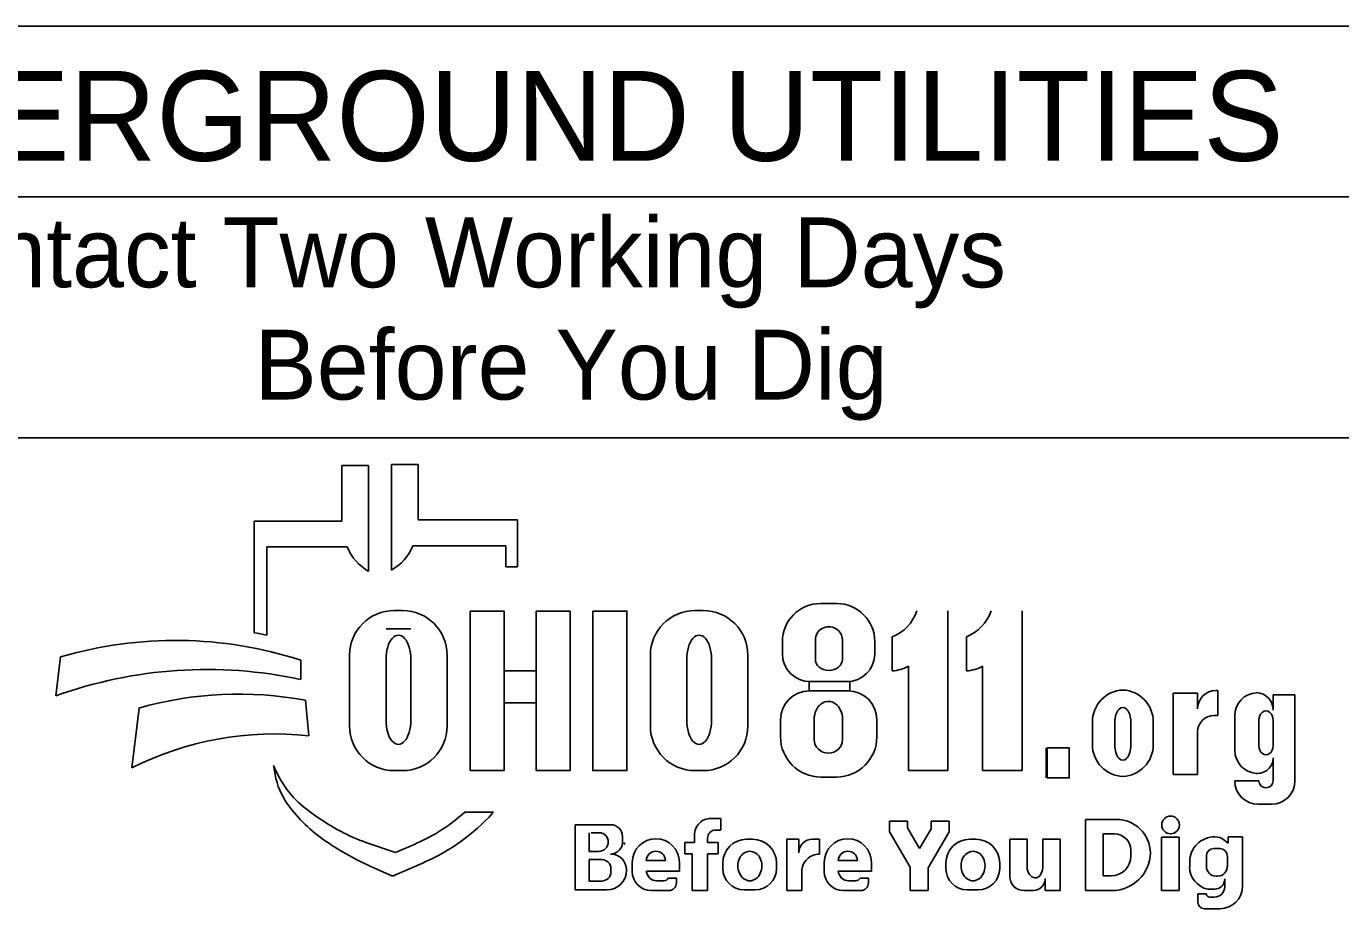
# Model space of a CAD drawing. Extents: x -1.2 to 34, y -8.5 to 22.
# Drawn here: x 15.565 to 18.2, y 1.501 to 3.27 of the extents above; entities that cross this region are included whole.
import ezdxf

# ---------------------------------------------------------------- set-up
doc = ezdxf.new("R2010")
doc.units = 0
doc.layers.add('SH_Data', color=7, linetype='Continuous')
doc.layers.add('SH_Text', color=7, linetype='Continuous')

msp = doc.modelspace()

# ---------------------------------------------------------------- linework, layer by layer
at = {"layer": 'SH_Data'}
for p, q in [((19.0916, 3.2703), (14.8416, 3.2703)), ((14.8416, 2.9287), (19.0916, 2.9287)), ((14.8416, 2.4453), (19.0916, 2.4453))]:
    msp.add_line(p, q, dxfattribs=at)
at = {"layer": 'SH_Text'}
for p, q in [((16.1976, 2.2783), (16.1976, 2.3897)), ((16.1976, 2.3897), (16.2513, 2.3897)), ((16.2513, 2.3897), (16.2513, 2.1777)), ((16.2969, 2.18), (16.2969, 2.3921)), ((16.2969, 2.3921), (16.3506, 2.3921)), ((16.3506, 2.3921), (16.3506, 2.2806)), ((16.0217, 2.0544), (16.0217, 2.2783)), ((16.0217, 2.2783), (16.1976, 2.2783)), ((16.3506, 2.2806), (16.5498, 2.2806)), ((16.5498, 2.2806), (16.5498, 2.1868)), ((16.0469, 2.2268), (16.0469, 2.05)), ((16.208, 2.2268), (16.0469, 2.2268)), ((16.5265, 2.2291), (16.3402, 2.2291)), ((16.5265, 2.1868), (16.5265, 2.2291)), ((16.5498, 2.1868), (16.5265, 2.1868)), ((17.1572, 2.1131), (17.1899, 2.1131)), ((16.3026, 2.0991), (16.3192, 2.0991)), ((16.9057, 2.0991), (16.9222, 2.0991)), ((17.4127, 2.0986), (17.4127, 1.7787)), ((17.5616, 2.0986), (17.5616, 1.7787)), ((16.3359, 2.0621), (16.2861, 2.0621)), ((17.0809, 2.0125), (17.0809, 2.0368)), ((17.147, 2.0011), (17.147, 2.0404)), ((17.2012, 2.0404), (17.2012, 2.0011)), ((17.2662, 2.0368), (17.2662, 2.0125)), ((17.3011, 1.9779), (17.3011, 2.0461)), ((17.45, 1.9779), (17.45, 2.0461)), ((15.6243, 1.9281), (15.6337, 2.0062)), ((16.2132, 1.8676), (16.2132, 2.0096)), ((16.4086, 2.0096), (16.4086, 1.8676)), ((16.8162, 1.8676), (16.8162, 2.0096)), ((17.0117, 2.0096), (17.0117, 1.8676)), ((16.115, 1.9997), (16.115, 1.9609)), ((16.2861, 1.879), (16.2861, 2.0013)), ((16.3359, 2.0013), (16.3359, 1.879)), ((16.8891, 1.879), (16.8891, 2.0013)), ((16.9389, 2.0013), (16.9389, 1.879)), ((17.3335, 1.7787), (17.3335, 1.9873)), ((17.4823, 1.7787), (17.4823, 1.9873)), ((17.2102, 1.9565), (17.1369, 1.9565)), ((17.1351, 1.9382), (17.2124, 1.9382)), ((17.9134, 1.9335), (17.8645, 1.9335)), ((17.8645, 1.9335), (17.8645, 1.7706)), ((17.9134, 1.902), (17.9134, 1.9335)), ((17.9541, 1.9387), (17.9501, 1.9387)), ((17.9541, 1.8888), (17.9541, 1.9387)), ((18.0649, 1.8994), (18.0649, 1.9304)), ((18.0649, 1.9304), (18.1085, 1.9304)), ((18.1085, 1.9304), (18.1085, 1.7575)), ((15.7761, 1.7835), (15.7908, 1.9037)), ((16.1249, 1.9191), (16.1312, 1.8481)), ((17.0772, 1.8462), (17.0772, 1.8803)), ((17.1447, 1.8403), (17.1447, 1.8812)), ((17.2015, 1.8812), (17.2015, 1.8403)), ((17.2703, 1.8803), (17.2703, 1.8462)), ((17.7025, 1.8304), (17.7025, 1.8758)), ((17.7476, 1.8296), (17.7476, 1.8758)), ((17.7797, 1.8758), (17.7797, 1.8296)), ((17.8247, 1.8758), (17.8247, 1.8304)), ((17.9464, 1.8888), (17.9541, 1.8888)), ((17.988, 1.8189), (17.988, 1.8885)), ((18.0364, 1.8282), (18.0364, 1.8793)), ((18.0649, 1.8793), (18.0649, 1.8282)), ((17.9134, 1.7706), (17.9134, 1.8558)), ((17.6096, 1.8237), (17.6096, 1.7636)), ((18.0649, 1.7575), (18.0649, 1.8039)), ((16.0638, 1.7706), (16.0608, 1.7886)), ((16.3192, 1.7781), (16.3026, 1.7781)), ((16.9222, 1.7781), (16.9057, 1.7781)), ((17.4127, 1.7787), (17.3335, 1.7787)), ((17.5616, 1.7787), (17.4823, 1.7787)), ((17.8645, 1.7706), (17.9134, 1.7706)), ((17.1893, 1.7653), (17.1581, 1.7653)), ((17.988, 1.7575), (18.0364, 1.7575)), ((16.4441, 1.6948), (16.5015, 1.6948)), ((18.0617, 1.7107), (18.0348, 1.7107)), ((16.6654, 1.539), (16.6654, 1.6697)), ((16.6654, 1.6697), (16.7366, 1.6697)), ((16.938, 1.6825), (16.9574, 1.6825)), ((16.9574, 1.6825), (16.9574, 1.6595)), ((17.296, 1.6769), (17.3318, 1.6769)), ((17.296, 1.6555), (17.296, 1.6769)), ((17.3318, 1.6769), (17.3318, 1.6633)), ((17.3318, 1.6633), (17.3559, 1.6219)), ((17.3559, 1.6219), (17.3791, 1.6618)), ((17.3791, 1.6618), (17.3791, 1.6769)), ((17.3791, 1.6769), (17.415, 1.6769)), ((17.415, 1.6769), (17.415, 1.6555)), ((17.6884, 1.6805), (17.7507, 1.6805)), ((17.6884, 1.5378), (17.6884, 1.6805)), ((16.2457, 1.6344), (16.3051, 1.6139)), ((16.6934, 1.6163), (16.6934, 1.6532)), ((16.7186, 1.6532), (16.6973, 1.6532)), ((16.7603, 1.646), (16.7603, 1.6381)), ((16.8854, 1.6112), (16.8854, 1.6341)), ((16.8854, 1.6341), (16.9047, 1.6341)), ((16.9047, 1.6341), (16.9047, 1.6446)), ((16.9308, 1.6426), (16.9308, 1.6341)), ((16.9308, 1.6341), (16.9524, 1.6341)), ((16.9574, 1.6591), (16.9473, 1.6591)), ((16.9524, 1.6341), (16.9524, 1.6112)), ((17.0092, 1.6407), (17.0213, 1.6407)), ((17.0895, 1.5378), (17.0895, 1.6405)), ((17.0895, 1.6405), (17.114, 1.6405)), ((17.114, 1.6405), (17.114, 1.6136)), ((17.1412, 1.6405), (17.1551, 1.6405)), ((17.1551, 1.6405), (17.1551, 1.6108)), ((17.3373, 1.5845), (17.296, 1.6555)), ((17.415, 1.6555), (17.3729, 1.5831)), ((17.4566, 1.6407), (17.4688, 1.6407)), ((17.5368, 1.6407), (17.5715, 1.6407)), ((17.5368, 1.5662), (17.5368, 1.6407)), ((17.5715, 1.6407), (17.5715, 1.5854)), ((17.6029, 1.5837), (17.6029, 1.6407)), ((17.6029, 1.6407), (17.6377, 1.6407)), ((17.6377, 1.6407), (17.6377, 1.5378)), ((17.7244, 1.5672), (17.7244, 1.6513)), ((17.7244, 1.6513), (17.7469, 1.6513)), ((17.8411, 1.6449), (17.8767, 1.6449)), ((17.8411, 1.5378), (17.8411, 1.6449)), ((17.8767, 1.6449), (17.8767, 1.5378)), ((17.9662, 1.6393), (17.9748, 1.6327)), ((17.9748, 1.6453), (18.0036, 1.6453)), ((17.9748, 1.6327), (17.9748, 1.6453)), ((17.9748, 1.6453), (18.0036, 1.6453)), ((18.0036, 1.6453), (18.0036, 1.5467)), ((16.3051, 1.6139), (16.3461, 1.6317)), ((16.7128, 1.6163), (16.6934, 1.6163)), ((16.9003, 1.6112), (16.8854, 1.6112)), ((16.9003, 1.5378), (16.9003, 1.6112)), ((16.9524, 1.6112), (16.9308, 1.6112)), ((16.9308, 1.6112), (16.9308, 1.5378)), ((17.7795, 1.6186), (17.7795, 1.6067)), ((17.9457, 1.6219), (17.9584, 1.6219)), ((16.2991, 1.5669), (16.2617, 1.5833)), ((16.3624, 1.5943), (16.2991, 1.5669)), ((16.6934, 1.5568), (16.6934, 1.5997)), ((16.6934, 1.5997), (16.7189, 1.5997)), ((16.737, 1.5816), (16.737, 1.5752)), ((16.78, 1.5758), (16.78, 1.5942)), ((16.8465, 1.5982), (16.808, 1.5982)), ((16.8745, 1.5942), (16.8745, 1.5765)), ((16.9614, 1.5821), (16.9614, 1.5929)), ((17.0691, 1.5929), (17.0691, 1.5821)), ((17.1649, 1.5758), (17.1649, 1.5942)), ((17.2315, 1.5982), (17.1929, 1.5982)), ((17.2594, 1.5942), (17.2594, 1.5765)), ((17.3373, 1.5378), (17.3373, 1.5845)), ((17.3729, 1.5831), (17.3729, 1.5378)), ((17.4088, 1.5821), (17.4088, 1.5929)), ((17.5166, 1.5929), (17.5166, 1.5821)), ((17.8976, 1.5853), (17.8976, 1.5954)), ((17.9311, 1.586), (17.9311, 1.6073)), ((17.9731, 1.6073), (17.9731, 1.586)), ((16.7187, 1.5568), (16.6934, 1.5568)), ((16.7684, 1.5787), (16.7684, 1.5783)), ((16.8745, 1.5765), (16.8081, 1.5765)), ((16.829, 1.5573), (16.8431, 1.5573)), ((16.8517, 1.5629), (16.8685, 1.5629)), ((16.8685, 1.5629), (16.8685, 1.553)), ((17.12, 1.5759), (17.12, 1.5378)), ((17.2594, 1.5765), (17.193, 1.5765)), ((17.2139, 1.5573), (17.228, 1.5573)), ((17.2366, 1.5629), (17.2535, 1.5629)), ((17.2535, 1.5629), (17.2535, 1.553)), ((17.608, 1.5378), (17.608, 1.5619)), ((17.74, 1.5672), (17.7244, 1.5672)), ((17.9537, 1.5667), (17.9504, 1.5667)), ((17.9679, 1.5457), (17.9679, 1.561)), ((16.7291, 1.539), (16.6654, 1.539)), ((16.8533, 1.5378), (16.8179, 1.5378)), ((16.9308, 1.5378), (16.9003, 1.5378)), ((17.0264, 1.5393), (17.0042, 1.5393)), ((17.12, 1.5378), (17.0895, 1.5378)), ((17.2382, 1.5378), (17.2028, 1.5378)), ((17.3729, 1.5378), (17.3373, 1.5378)), ((17.4738, 1.5393), (17.4516, 1.5393)), ((17.584, 1.5378), (17.5652, 1.5378)), ((17.6377, 1.5378), (17.608, 1.5378)), ((17.742, 1.5378), (17.6884, 1.5378)), ((17.8767, 1.5378), (17.8411, 1.5378)), ((17.9141, 1.5145), (17.9141, 1.5315)), ((17.9141, 1.5315), (17.9311, 1.5315)), ((17.9476, 1.5406), (17.9339, 1.5406)), ((17.9379, 1.5245), (17.9468, 1.5245)), ((17.9583, 1.5014), (17.9272, 1.5014))]:
    msp.add_line(p, q, dxfattribs=at)
for points in [[(16.4551, 2.098), (16.523, 2.098), (16.523, 1.7781), (16.4551, 1.7781)], [(16.5872, 2.098), (16.6552, 2.098), (16.6552, 1.7781), (16.5872, 1.7781)], [(16.7005, 2.098), (16.7693, 2.098), (16.7693, 1.7781), (16.7005, 1.7781)], [(16.523, 1.9781), (16.5872, 1.9781), (16.5872, 1.9141), (16.523, 1.9141)], [(17.1347, 1.9565), (17.2164, 1.9565), (17.2164, 1.938), (17.1347, 1.938)], [(17.6121, 1.8237), (17.6562, 1.8237), (17.6562, 1.7636), (17.6121, 1.7636)]]:
    msp.add_lwpolyline(points, close=True, dxfattribs=at)
msp.add_circle((17.8593, 1.6692), 0.0177, dxfattribs=at)
for centre, radius, start, end in [((16.2994, 2.2636), 0.0985, 201.9296, 240.7469), ((16.2488, 2.2659), 0.0985, 299.2531, 338.0704), ((17.1572, 2.0368), 0.0763, 90, 180), ((17.1899, 2.0368), 0.0763, 0, 90), ((16.3026, 2.0096), 0.0895, 90, 180), ((16.3192, 2.0096), 0.0895, 0, 90), ((16.9057, 2.0096), 0.0895, 90, 180), ((16.9222, 2.0096), 0.0895, 0, 90), ((17.2672, 2.1278), 0.0885, 292.5572, 340.7355), ((17.416, 2.1278), 0.0885, 292.5572, 340.7355), ((15.8638, 1.2201), 0.8191, 72.1402, 106.3144), ((15.8935, 1.2454), 0.8191, 79.2074, 81.0007), ((17.1369, 2.0125), 0.056, 180, 270), ((17.2102, 2.0125), 0.056, 270, 0), ((15.9268, 1.089), 0.8919, 77.8238, 109.8274), ((17.2932, 2.0661), 0.0885, 275.1733, 297.0931), ((17.442, 2.0661), 0.0885, 275.1733, 297.0931), ((15.9907, 1.1993), 0.7322, 79.44, 105.8467), ((17.1351, 1.8803), 0.0579, 90, 180), ((17.2124, 1.8803), 0.0579, 0, 90), ((17.7665, 1.8758), 0.064, 92.5886, 180), ((17.7607, 1.8758), 0.064, 0, 87.4114), ((17.9501, 1.902), 0.0367, 90, 180), ((18.0339, 1.8885), 0.0459, 92.6865, 180), ((18.0299, 1.8994), 0.0351, 0, 86.9262), ((17.9464, 1.8558), 0.033, 90, 180), ((16.0628, 1.2161), 0.6357, 83.8248, 116.8021), ((16.3026, 1.8676), 0.0895, 180, 270), ((16.3192, 1.8676), 0.0895, 270, 0), ((16.9057, 1.8676), 0.0895, 180, 270), ((16.9222, 1.8676), 0.0895, 270, 0), ((17.1581, 1.8462), 0.081, 180, 270), ((17.1893, 1.8462), 0.081, 270, 0), ((17.7665, 1.8304), 0.064, 180, 267.4114), ((17.7607, 1.8304), 0.064, 272.5886, 0), ((18.0343, 1.8189), 0.0463, 180, 265.7132), ((18.0337, 1.8039), 0.0313, 264.7825, 0), ((16.2482, 1.8607), 0.2008, 201.0457, 232.5314), ((16.2051, 1.7947), 0.1433, 189.6817, 216.0884), ((18.0348, 1.7575), 0.0468, 180, 270), ((18.0617, 1.7575), 0.0468, 270, 0), ((16.3388, 1.8922), 0.3088, 216.0884, 235.7167), ((16.4407, 2.1119), 0.5173, 232.5314, 241.794), ((16.2027, 1.9622), 0.3602, 293.4582, 312.0712), ((16.2027, 1.9622), 0.401, 293.4582, 317.8286), ((16.7366, 1.646), 0.0238, 0, 90), ((16.938, 1.649), 0.0335, 90, 187.5187), ((17.7507, 1.6123), 0.0682, 0.9944, 90), ((16.5053, 2.1364), 0.6044, 235.7167, 246.2325), ((16.3555, 1.9531), 0.3371, 241.794, 250.9821), ((16.7128, 1.635), 0.0187, 270, 2.0582), ((16.7146, 1.6363), 0.0169, 357.8325, 90), ((16.7362, 1.6353), 0.0243, 270, 6.6529), ((16.8272, 1.5942), 0.0473, 0, 180), ((16.9473, 1.6426), 0.0165, 90, 180), ((17.0092, 1.5929), 0.0478, 90, 180), ((17.0213, 1.5929), 0.0478, 0, 90), ((17.1409, 1.6136), 0.0269, 89.2449, 180), ((17.2121, 1.5942), 0.0473, 0, 180), ((17.4566, 1.5929), 0.0478, 90, 180), ((17.4688, 1.5929), 0.0478, 0, 90), ((17.7469, 1.6186), 0.0327, 0, 90), ((17.9475, 1.5954), 0.0499, 89.0934, 180), ((17.9489, 1.617), 0.0283, 52.1415, 91.2046), ((16.7363, 1.5789), 0.0321, 4.0748, 90), ((16.7468, 1.6338), 0.0175, 347.4023, 0), ((16.8273, 1.5972), 0.0193, 2.9632, 177.0368), ((17.1549, 1.5759), 0.0349, 89.6033, 180), ((17.2122, 1.5972), 0.0193, 2.9632, 177.0368), ((17.742, 1.6147), 0.0769, 270, 359.0635), ((17.9457, 1.6073), 0.0146, 90, 180), ((17.9584, 1.6073), 0.0146, 0, 90), ((16.7189, 1.5816), 0.0181, 0, 90), ((16.7354, 1.5787), 0.033, 0, 11.7502), ((17.0042, 1.5821), 0.0428, 180, 270), ((17.0264, 1.5821), 0.0428, 270, 0), ((17.4516, 1.5821), 0.0428, 180, 270), ((17.4738, 1.5821), 0.0428, 270, 0), ((17.74, 1.6067), 0.0395, 270, 0), ((17.9432, 1.5853), 0.0457, 180, 258.2203), ((17.9504, 1.586), 0.0193, 180, 270), ((17.9537, 1.586), 0.0193, 270, 0), ((16.7187, 1.5752), 0.0184, 270, 0), ((16.7291, 1.5783), 0.0393, 270, 0), ((16.8179, 1.5758), 0.038, 180, 270), ((16.829, 1.5783), 0.021, 184.827, 270), ((16.8431, 1.5667), 0.00938, 270, 335.9979), ((17.2028, 1.5758), 0.038, 180, 270), ((17.2139, 1.5783), 0.021, 184.827, 270), ((17.228, 1.5667), 0.00938, 270, 335.9979), ((17.5652, 1.5662), 0.0284, 180, 270), ((17.584, 1.5619), 0.024, 270, 0), ((17.9476, 1.5609), 0.0203, 270, 0), ((16.8533, 1.553), 0.0152, 270, 0), ((17.2382, 1.553), 0.0152, 270, 0), ((17.9379, 1.5313), 0.00682, 180, 270), ((17.9468, 1.5457), 0.0212, 270, 0), ((17.9583, 1.5467), 0.0453, 270, 0), ((17.9272, 1.5145), 0.0131, 180, 270)]:
    msp.add_arc(centre, radius, start, end, dxfattribs=at)
for centre, major_axis, ratio, start_param, end_param in [((17.1741, 2.0404), (0.0271, 0), 0.969373, 0, 3.141593), ((16.311, 2.0013), (0, 0.0484), 0.514403, 4.712389, 7.853982), ((16.914, 2.0013), (0, 0.0484), 0.514403, 4.712389, 7.853982), ((17.1741, 2.0011), (0.0271, 0), 0.818453, 3.141593, 6.283185), ((17.1731, 1.8812), (0, 0.0358), 0.794529, 4.712389, 7.853982), ((17.7636, 1.8758), (0, 0.0291), 0.553236, 4.712389, 7.853982), ((18.0506, 1.8793), (0, 0.0184), 0.777179, 4.712389, 7.853982), ((16.311, 1.879), (0, 0.0484), 0.514403, 1.570796, 4.712389), ((16.914, 1.879), (0, 0.0484), 0.514403, 1.570796, 4.712389), ((17.1731, 1.8403), (0.0284, 0), 0.959837, 3.141593, 6.283185), ((17.7636, 1.8296), (0, 0.0308), 0.522014, 1.570796, 4.712389), ((18.0506, 1.8282), (0, 0.0184), 0.777179, 1.570796, 4.712389), ((18.0506, 1.7575), (0.0143, 0), 0.959012, 3.141593, 6.283185), ((17.0157, 1.5875), (0, 0.029), 0.832186, 4.712389, 7.853982), ((17.4632, 1.5875), (0, 0.029), 0.832186, 4.712389, 7.853982), ((17.0157, 1.5875), (0, 0.0302), 0.797287, 1.570796, 4.712389), ((17.4632, 1.5875), (0, 0.0302), 0.797287, 1.570796, 4.712389), ((17.5872, 1.5861), (-0.0011, 0.0231), 0.679042, 1.570796, 4.575961)]:
    msp.add_ellipse(centre, major_axis=major_axis, ratio=ratio, start_param=start_param, end_param=end_param, dxfattribs=at)

# ---------------------------------------------------------------- texts
for s, height, p in [('UNDERGROUND UTILITIES', 0.18, (14.9697, 3.0006)), ('Contact Two Working Days', 0.14, (15.2612, 2.7471)), ('Before You Dig', 0.14, (16.0224, 2.5221))]:
    msp.add_text(s, height=height, dxfattribs=at).set_placement(p)

doc.saveas('drawing.dxf')
